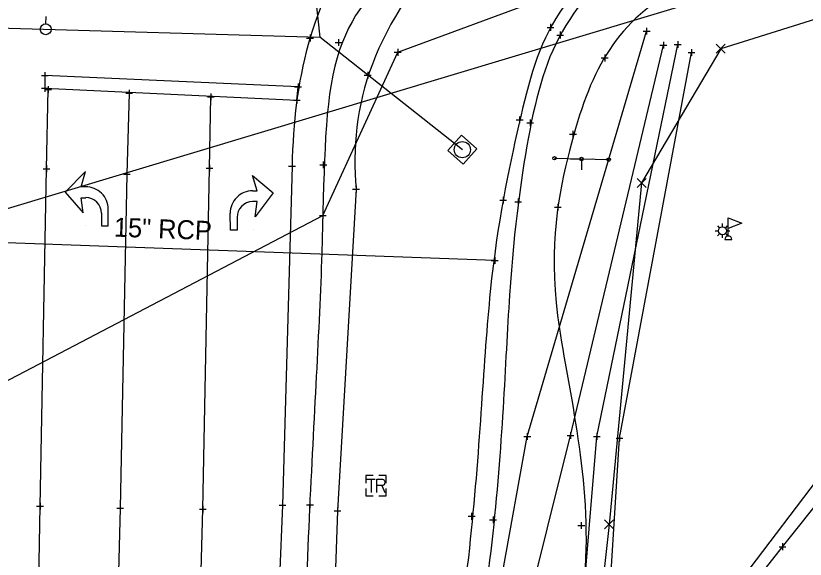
# Model space of a CAD drawing. Extents: x 1391912 to 1392597, y 304167 to 305226.
# Drawn here: x 1392322.5 to 1392438.8, y 304366.2 to 304446.3 of the extents above; entities that cross this region are included whole.
import ezdxf

# ---------------------------------------------------------------- set-up
doc = ezdxf.new("R2010")
doc.units = 0
for name, color, linetype in [('_CIVIL_CONSTRUCTION', 7, 'Continuous'), ('DR_X_Storm_Sewer', 7, 'Continuous'), ('DV_X_Property_Line', 7, 'Continuous'), ('DV_X_Section_VMS_Line', 7, 'Continuous'), ('PM_X_Channelizing_Line', 7, 'Continuous'), ('PM_X_CL_Double_Solid', 7, 'Continuous'), ('PM_X_Edge_Line', 7, 'Continuous'), ('PM_X_Stop_Line', 7, 'Continuous'), ('PV_X_EOP', 7, 'Continuous'), ('PV_X_Shoulder_Aggregate', 7, 'Continuous'), ('RW_X_CL_100_Bearings', 7, 'Continuous'), ('RW_X_CL_100_Cardinal_Points', 7, 'Continuous'), ('RW_X_Esmt_SH', 7, 'Continuous'), ('SC_Scratch6', 7, 'Continuous'), ('SG_X_Heads', 7, 'Continuous'), ('SG_X_Messenger_Wire', 7, 'Continuous'), ('SN_X_Private', 7, 'Continuous'), ('SV_X_Break_Lines', 7, 'Continuous'), ('SV_X_Terrain_Boundary', 7, 'Continuous'), ('SV_X_Text', 7, 'Continuous'), ('SV_X_Toe_of_Slope', 7, 'Continuous'), ('SV_X_Top_of_Bank', 7, 'Continuous'), ('UT_X_FO', 7, 'Continuous'), ('UT_X_Gas', 7, 'Continuous'), ('UT_X_Overhead_Combined', 7, 'Continuous'), ('UT_X_Sanitary_Line', 7, 'Continuous')]:
    doc.layers.add(name, color=color, linetype=linetype)

msp = doc.modelspace()

# ---------------------------------------------------------------- linework, layer by layer
at = {"layer": '_CIVIL_CONSTRUCTION'}
for p, q in [((1392404.25, 304425.18), (1392407.45, 304425.19)), ((1392405.85, 304425.19), (1392405.85, 304423.59)), ((1392426.62, 304415.19), (1392426.62, 304415.67)), ((1392425.56, 304414.6), (1392426.04, 304414.6)), ((1392425.87, 304415.35), (1392426.2, 304415.01)), ((1392427.04, 304415.01), (1392427.38, 304415.35)), ((1392427.21, 304414.6), (1392427.69, 304414.6)), ((1392425.87, 304413.84), (1392426.21, 304414.18)), ((1392426.62, 304413.54), (1392426.62, 304414.01)), ((1392427.04, 304414.18), (1392427.37, 304413.84))]:
    msp.add_line(p, q, dxfattribs=at)
msp.add_circle((1392426.62, 304414.6), 0.588, dxfattribs=at)
at = {"layer": 'DR_X_Storm_Sewer'}
msp.add_line((1392393.06, 304410.21), (1392288.79, 304414), dxfattribs=at)
at = {"layer": 'DV_X_Property_Line'}
for p, q in [((1392332.77, 304423.32), (1392329.77, 304420.28)), ((1392332.11, 304421.08), (1392332.77, 304423.32)), ((1392332.77, 304423.32), (1392332.77, 304423.32)), ((1392357.35, 304422.74), (1392357.35, 304422.74)), ((1392358.05, 304420.51), (1392357.35, 304422.74)), ((1392357.35, 304422.74), (1392360.39, 304420.22)), ((1392329.77, 304420.28), (1392332.44, 304417.24)), ((1392332.77, 304421.08), (1392332.11, 304421.08)), ((1392357.38, 304420.5), (1392358.05, 304420.51)), ((1392360.39, 304420.22), (1392357.76, 304416.67)), ((1392332.44, 304417.24), (1392332.11, 304419.48)), ((1392332.11, 304419.48), (1392332.81, 304419.48)), ((1392336.11, 304415.32), (1392336.11, 304417.8)), ((1392358.07, 304418.91), (1392357.37, 304418.9)), ((1392357.76, 304416.67), (1392358.07, 304418.91)), ((1392335.11, 304417.19), (1392335.11, 304415.32)), ((1392354.12, 304414.7), (1392354.09, 304417.18)), ((1392355.1, 304416.58), (1392355.12, 304414.71)), ((1392332.77, 304415.32), (1392332.77, 304415.32)), ((1392335.11, 304415.32), (1392336.11, 304415.32)), ((1392355.12, 304414.71), (1392354.12, 304414.7)), ((1392357.46, 304414.74), (1392357.46, 304414.74))]:
    msp.add_line(p, q, dxfattribs=at)
for centre, radius, start, end in [((1392332.83, 304417.8), 3.28, 0, 90.9085), ((1392357.37, 304417.22), 3.28, 89.8199, 180.7284), ((1392332.81, 304417.19), 2.3, 0, 90), ((1392357.4, 304416.6), 2.3, 90.7284, 180.7284)]:
    msp.add_arc(centre, radius, start, end, dxfattribs=at)
at = {"layer": 'DV_X_Section_VMS_Line'}
for p, q in [((1392425.69, 304440.78), (1392427.02, 304442.11)), ((1392425.69, 304442.11), (1392427.02, 304440.78)), ((1392414.04, 304420.99), (1392415.37, 304422.32)), ((1392414.04, 304422.32), (1392415.37, 304420.99)), ((1392409.24, 304370.62), (1392410.58, 304371.96)), ((1392409.24, 304371.96), (1392410.58, 304370.62))]:
    msp.add_line(p, q, dxfattribs=at)
at = {"layer": 'PM_X_Channelizing_Line'}
for points in [[(1392339.19, 304434.91), (1392338.84, 304422.93), (1392337.86, 304373.67), (1392336.91, 304335.98)], [(1392349.04, 304335.4), (1392350.06, 304373.54), (1392351.03, 304423.84), (1392351.23, 304434.34)]]:
    msp.add_lwpolyline(points, dxfattribs=at)
at = {"layer": 'PM_X_CL_Double_Solid'}
msp.add_lwpolyline([(1392325.19, 304324.71), (1392326.06, 304374), (1392327, 304423.76), (1392327.25, 304435.44)], dxfattribs=at)
at = {"layer": 'PM_X_Edge_Line'}
for p, q in [((1392363.19, 304424.13), (1392361.8, 304374.11)), ((1392361.8, 304374.11), (1392359.73, 304323.64))]:
    msp.add_line(p, q, dxfattribs=at)
msp.add_open_spline([(1392413.88, 304484.19), (1392403.75, 304480.87), (1392389.02, 304473.91), (1392372.2, 304458.99), (1392364.64, 304442.07), (1392363.37, 304430.73), (1392363.19, 304424.13)], degree=3, dxfattribs=at)
at = {"layer": 'PM_X_Stop_Line'}
msp.add_lwpolyline([(1392363.91, 304433.87), (1392364.08, 304435.81), (1392326.77, 304437.48), (1392326.79, 304435.61)], close=True, dxfattribs=at)
at = {"layer": 'PV_X_EOP'}
msp.add_open_spline([(1392378.24, 304452.75), (1392374.59, 304449.68), (1392367.73, 304441.64), (1392368.05, 304412.94), (1392365.56, 304374.27), (1392364.51, 304340.35), (1392363.84, 304323.44)], degree=3, dxfattribs=at)
at = {"layer": 'PV_X_Shoulder_Aggregate'}
for p, q in [((1392372.62, 304420.74), (1392369.9, 304373.3)), ((1392369.9, 304373.3), (1392368.06, 304323.26))]:
    msp.add_line(p, q, dxfattribs=at)
msp.add_open_spline([(1392407.47, 304470.58), (1392398.57, 304466.98), (1392385.86, 304458.06), (1392373.18, 304439.16), (1392372.13, 304426.71), (1392372.62, 304420.74)], degree=3, dxfattribs=at)
at = {"layer": 'RW_X_CL_100_Bearings'}
for p, q in [((1392427.48, 304413.83), (1392427.48, 304416.53)), ((1392427.48, 304416.53), (1392429.48, 304415.73)), ((1392429.48, 304415.73), (1392427.48, 304414.93)), ((1392427.48, 304414.93), (1392427.48, 304414.93)), ((1392426.98, 304413.33), (1392427.98, 304413.33))]:
    msp.add_line(p, q, dxfattribs=at)
msp.add_arc((1392427.48, 304413.33), 0.5, 0, 180, dxfattribs=at)
at = {"layer": 'RW_X_CL_100_Cardinal_Points'}
msp.add_line((1392375.57, 304376.99), (1392375.57, 304376.99), dxfattribs=at)
for points in [[(1392375.17, 304378.49), (1392374.07, 304378.49), (1392374.07, 304377.39)], [(1392377.07, 304377.39), (1392377.07, 304378.49), (1392375.97, 304378.49)], [(1392374.21, 304377.99), (1392375.45, 304377.99)], [(1392374.84, 304377.99), (1392374.84, 304375.99)], [(1392375.68, 304375.99), (1392375.68, 304377.99), (1392376.43, 304377.99), (1392376.51, 304377.97), (1392376.62, 304377.94), (1392376.67, 304377.91), (1392376.72, 304377.88), (1392376.78, 304377.8), (1392376.83, 304377.72), (1392376.86, 304377.6), (1392376.86, 304377.41), (1392376.84, 304377.34), (1392376.81, 304377.25), (1392376.75, 304377.14), (1392376.69, 304377.09), (1392376.64, 304377.06), (1392376.61, 304377.04), (1392376.56, 304377.03), (1392376.42, 304377.01), (1392375.68, 304377.01)], [(1392374.07, 304376.59), (1392374.07, 304375.49), (1392375.17, 304375.49)], [(1392375.97, 304375.49), (1392377.07, 304375.49), (1392377.07, 304376.59)], [(1392376.42, 304377.01), (1392376.86, 304375.99)]]:
    msp.add_lwpolyline(points, dxfattribs=at)
at = {"layer": 'RW_X_Esmt_SH'}
for p, q in [((1392400.78, 304444.6), (1392401.78, 304444.6)), ((1392401.28, 304445.1), (1392401.28, 304444.1)), ((1392401.28, 304444.6), (1392401.28, 304444.6)), ((1392415.44, 304444.55), (1392415.44, 304443.55)), ((1392365.85, 304443.53), (1392365.85, 304442.53)), ((1392402.2, 304443.47), (1392403.2, 304443.47)), ((1392402.7, 304443.97), (1392402.7, 304442.97)), ((1392402.7, 304443.47), (1392402.7, 304443.47)), ((1392414.94, 304444.05), (1392415.94, 304444.05)), ((1392415.44, 304444.05), (1392415.44, 304444.05)), ((1392365.35, 304443.03), (1392366.35, 304443.03)), ((1392365.85, 304443.03), (1392365.85, 304443.03)), ((1392369.55, 304442.38), (1392370.55, 304442.38)), ((1392370.05, 304442.88), (1392370.05, 304441.88)), ((1392370.05, 304442.38), (1392370.05, 304442.38)), ((1392417.91, 304442.46), (1392417.91, 304441.46)), ((1392420.02, 304442.58), (1392420.02, 304441.58)), ((1392378.76, 304441.42), (1392378.76, 304440.42)), ((1392417.41, 304441.96), (1392418.41, 304441.96)), ((1392417.91, 304441.96), (1392417.91, 304441.96)), ((1392419.52, 304442.08), (1392420.52, 304442.08)), ((1392420.02, 304442.08), (1392420.02, 304442.08)), ((1392422.06, 304441.39), (1392422.06, 304440.39)), ((1392378.26, 304440.92), (1392379.26, 304440.92)), ((1392378.76, 304440.92), (1392378.76, 304440.92)), ((1392408.76, 304440.09), (1392409.76, 304440.09)), ((1392409.26, 304440.59), (1392409.26, 304439.59)), ((1392409.26, 304440.09), (1392409.26, 304440.09)), ((1392421.56, 304440.89), (1392422.56, 304440.89)), ((1392422.06, 304440.89), (1392422.06, 304440.89)), ((1392326.77, 304437.98), (1392326.77, 304436.98)), ((1392374.34, 304438.06), (1392374.34, 304437.06)), ((1392326.27, 304437.48), (1392327.27, 304437.48)), ((1392326.77, 304437.48), (1392326.77, 304437.48)), ((1392373.84, 304437.56), (1392374.84, 304437.56)), ((1392374.34, 304437.56), (1392374.34, 304437.56)), ((1392326.29, 304435.61), (1392327.29, 304435.61)), ((1392326.75, 304435.44), (1392327.75, 304435.44)), ((1392326.79, 304436.11), (1392326.79, 304435.11)), ((1392326.79, 304435.61), (1392326.79, 304435.61)), ((1392327.25, 304435.94), (1392327.25, 304434.94)), ((1392327.25, 304435.44), (1392327.25, 304435.44)), ((1392339.19, 304435.41), (1392339.19, 304434.41)), ((1392363.58, 304435.81), (1392364.58, 304435.81)), ((1392364.08, 304436.31), (1392364.08, 304435.31)), ((1392364.08, 304435.81), (1392364.08, 304435.81)), ((1392338.69, 304434.91), (1392339.69, 304434.91)), ((1392339.19, 304434.91), (1392339.19, 304434.91)), ((1392350.73, 304434.34), (1392351.73, 304434.34)), ((1392351.23, 304434.84), (1392351.23, 304433.84)), ((1392351.23, 304434.34), (1392351.23, 304434.34)), ((1392363.91, 304434.37), (1392363.91, 304433.37)), ((1392363.41, 304433.87), (1392364.41, 304433.87)), ((1392363.91, 304433.87), (1392363.91, 304433.87)), ((1392396.23, 304430.95), (1392397.23, 304430.95)), ((1392396.73, 304431.45), (1392396.73, 304430.45)), ((1392396.73, 304430.95), (1392396.73, 304430.95)), ((1392398.27, 304431.01), (1392398.27, 304430.01)), ((1392397.77, 304430.51), (1392398.77, 304430.51)), ((1392398.27, 304430.51), (1392398.27, 304430.51)), ((1392404.09, 304428.86), (1392405.09, 304428.86)), ((1392404.59, 304429.36), (1392404.59, 304428.36)), ((1392404.59, 304428.86), (1392404.59, 304428.86)), ((1392367.8, 304424.82), (1392367.8, 304423.82)), ((1392326.5, 304423.76), (1392327.5, 304423.76)), ((1392327, 304424.26), (1392327, 304423.26)), ((1392327, 304423.76), (1392327, 304423.76)), ((1392350.53, 304423.84), (1392351.53, 304423.84)), ((1392351.03, 304424.34), (1392351.03, 304423.34)), ((1392351.03, 304423.84), (1392351.03, 304423.84)), ((1392362.69, 304424.13), (1392363.69, 304424.13)), ((1392363.19, 304424.63), (1392363.19, 304423.63)), ((1392363.19, 304424.13), (1392363.19, 304424.13)), ((1392367.3, 304424.32), (1392368.3, 304424.32)), ((1392367.8, 304424.32), (1392367.8, 304424.32)), ((1392338.34, 304422.93), (1392339.34, 304422.93)), ((1392338.84, 304423.43), (1392338.84, 304422.43)), ((1392338.84, 304422.93), (1392338.84, 304422.93)), ((1392372.12, 304420.74), (1392373.12, 304420.74)), ((1392372.62, 304421.24), (1392372.62, 304420.24)), ((1392372.62, 304420.74), (1392372.62, 304420.74)), ((1392393.8, 304419.12), (1392394.8, 304419.12)), ((1392394.3, 304419.62), (1392394.3, 304418.62)), ((1392394.3, 304419.12), (1392394.3, 304419.12)), ((1392396.51, 304419.37), (1392396.51, 304418.37)), ((1392396.01, 304418.87), (1392397.01, 304418.87)), ((1392396.51, 304418.87), (1392396.51, 304418.87)), ((1392401.86, 304418.08), (1392402.86, 304418.08)), ((1392402.36, 304418.58), (1392402.36, 304417.58)), ((1392402.36, 304418.08), (1392402.36, 304418.08)), ((1392367.22, 304416.84), (1392368.22, 304416.84)), ((1392367.72, 304417.34), (1392367.72, 304416.34)), ((1392367.72, 304416.84), (1392367.72, 304416.84)), ((1392392.56, 304410.21), (1392393.56, 304410.21)), ((1392393.06, 304410.71), (1392393.06, 304409.71)), ((1392393.06, 304410.21), (1392393.06, 304410.21)), ((1392397.36, 304384.26), (1392398.36, 304384.26)), ((1392397.86, 304384.76), (1392397.86, 304383.76)), ((1392397.86, 304384.26), (1392397.86, 304384.26)), ((1392403.71, 304384.41), (1392404.71, 304384.41)), ((1392404.21, 304384.91), (1392404.21, 304383.91)), ((1392404.21, 304384.41), (1392404.21, 304384.41)), ((1392407.62, 304384.25), (1392408.62, 304384.25)), ((1392408.12, 304384.75), (1392408.12, 304383.75)), ((1392408.12, 304384.25), (1392408.12, 304384.25)), ((1392411.45, 304384.53), (1392411.45, 304383.53)), ((1392410.95, 304384.03), (1392411.95, 304384.03)), ((1392411.45, 304384.03), (1392411.45, 304384.03)), ((1392325.56, 304374), (1392326.56, 304374)), ((1392326.06, 304374.5), (1392326.06, 304373.5)), ((1392326.06, 304374), (1392326.06, 304374)), ((1392337.36, 304373.67), (1392338.36, 304373.67)), ((1392337.86, 304374.17), (1392337.86, 304373.17)), ((1392337.86, 304373.67), (1392337.86, 304373.67)), ((1392350.06, 304374.04), (1392350.06, 304373.04)), ((1392361.3, 304374.11), (1392362.3, 304374.11)), ((1392361.8, 304374.61), (1392361.8, 304373.61)), ((1392361.8, 304374.11), (1392361.8, 304374.11)), ((1392365.34, 304374.18), (1392366.34, 304374.18)), ((1392365.84, 304374.68), (1392365.84, 304373.68)), ((1392365.84, 304374.18), (1392365.84, 304374.18)), ((1392369.9, 304373.8), (1392369.9, 304372.8)), ((1392349.56, 304373.54), (1392350.56, 304373.54)), ((1392350.06, 304373.54), (1392350.06, 304373.54)), ((1392369.4, 304373.3), (1392370.4, 304373.3)), ((1392369.9, 304373.3), (1392369.9, 304373.3)), ((1392389.16, 304372.49), (1392390.16, 304372.49)), ((1392389.66, 304372.99), (1392389.66, 304371.99)), ((1392389.66, 304372.49), (1392389.66, 304372.49)), ((1392392.81, 304372.47), (1392392.81, 304371.47)), ((1392392.31, 304371.97), (1392393.31, 304371.97)), ((1392392.81, 304371.97), (1392392.81, 304371.97)), ((1392405.82, 304371.64), (1392405.82, 304370.64)), ((1392405.32, 304371.14), (1392406.32, 304371.14)), ((1392405.82, 304371.14), (1392405.82, 304371.14)), ((1392434.96, 304368.01), (1392435.96, 304368.01)), ((1392435.46, 304368.51), (1392435.46, 304367.51)), ((1392435.46, 304368.01), (1392435.46, 304368.01))]:
    msp.add_line(p, q, dxfattribs=at)
at = {"layer": 'SC_Scratch6'}
msp.add_lwpolyline([(1392386.17, 304426.46), (1392388.4, 304424.44), (1392390.41, 304426.67), (1392388.18, 304428.68)], close=True, dxfattribs=at)
msp.add_circle((1392388.29, 304426.56), 1.2, dxfattribs=at)
at = {"layer": 'SG_X_Heads'}
msp.add_line((1392326.93, 304445.11), (1392326.97, 304446.21), dxfattribs=at)
msp.add_circle((1392326.9, 304444.32), 0.8, dxfattribs=at)
at = {"layer": 'SG_X_Messenger_Wire'}
for p in [(1392361.08, 304501.95), (1392307.57, 304444.87), (1392388.29, 304426.56)]:
    msp.add_line(p, (1392367.29, 304443.16), dxfattribs=at)
at = {"layer": 'SN_X_Private'}
msp.add_line((1392401.85, 304425.29), (1392409.85, 304425.09), dxfattribs=at)
for centre in [(1392401.85, 304425.29), (1392405.85, 304425.19), (1392409.85, 304425.09)]:
    msp.add_circle(centre, 0.25, dxfattribs=at)
at = {"layer": 'SV_X_Break_Lines'}
msp.add_open_spline([(1392439.02, 304468.35), (1392430.22, 304466.36), (1392417.03, 304460.14), (1392402.39, 304445.83), (1392398.08, 304431.17), (1392394.86, 304407.24), (1392393.94, 304370.59), (1392388.07, 304338.52), (1392384.62, 304321.92)], degree=3, dxfattribs=at)
at = {"layer": 'SV_X_Terrain_Boundary'}
msp.add_lwpolyline([(1392444.41, 304447.07), (1392426.36, 304441.44), (1392414.71, 304421.65), (1392409.91, 304371.29), (1392404.17, 304319.57), (1392396.72, 304320.72), (1392384.62, 304321.92), (1392382.8, 304322.14), (1392368.06, 304323.26), (1392363.84, 304323.44), (1392359.73, 304323.64), (1392349.04, 304335.4), (1392336.91, 304335.98), (1392325.19, 304324.71), (1392313.17, 304324.96)], dxfattribs=at)
at = {"layer": 'SV_X_Toe_of_Slope'}
msp.add_open_spline([(1392438.7, 304469.65), (1392429.7, 304467.69), (1392416.24, 304461.41), (1392400.71, 304446.97), (1392396.8, 304431.68), (1392391.77, 304407.83), (1392390.55, 304371.01), (1392385.4, 304338.88), (1392382.8, 304322.14)], degree=3, dxfattribs=at)
at = {"layer": 'SV_X_Top_of_Bank'}
msp.add_open_spline([(1392421.16, 304450.78), (1392415.89, 304448.41), (1392409.07, 304441.73), (1392404.42, 304429.29), (1392399.45, 304406.29), (1392410.44, 304369.54), (1392401.99, 304337.41), (1392396.72, 304320.72)], degree=3, dxfattribs=at)
at = {"layer": 'UT_X_FO'}
for points in [[(1392388.27, 304325.85), (1392390.46, 304343.36), (1392397.86, 304384.26), (1392415.44, 304444.05)], [(1392391.7, 304325.3), (1392393.97, 304343.15), (1392404.21, 304384.41), (1392417.91, 304441.96)], [(1392402.42, 304316.01), (1392404.68, 304342.84), (1392408.12, 304384.25), (1392420.02, 304442.08)], [(1392407.36, 304318.6), (1392411.45, 304384.03), (1392422.06, 304440.89)]]:
    msp.add_lwpolyline(points, dxfattribs=at)
at = {"layer": 'UT_X_Gas'}
for points in [[(1392209.2, 304382.67), (1392248.36, 304369.77), (1392271.27, 304367.91), (1392291.41, 304368.17), (1392295.27, 304374.44), (1392298.64, 304380.68), (1392367.72, 304416.84), (1392378.76, 304440.92), (1392400.63, 304449.06), (1392408.05, 304456.92), (1392440.45, 304472.3), (1392459.13, 304475.15), (1392487.25, 304485.31), (1392492.6, 304487.47)], [(1392399.55, 304321.52), (1392415.67, 304342.75), (1392435.46, 304368.01), (1392455.37, 304392.91), (1392476.59, 304421.48), (1392493.88, 304443.91)]]:
    msp.add_lwpolyline(points, dxfattribs=at)
at = {"layer": 'UT_X_Overhead_Combined'}
msp.add_line((1392165.2, 304370.85), (1392586.59, 304497.87), dxfattribs=at)
at = {"layer": 'UT_X_Sanitary_Line'}
msp.add_line((1392394.73, 304317.39), (1392509.85, 304469.25), dxfattribs=at)

# ---------------------------------------------------------------- texts
at = {"layer": 'SV_X_Text'}
msp.add_text('15" RCP', height=2.8, rotation=357.9167, dxfattribs=at).set_placement((1392336.9, 304413.75))

doc.saveas('drawing.dxf')
